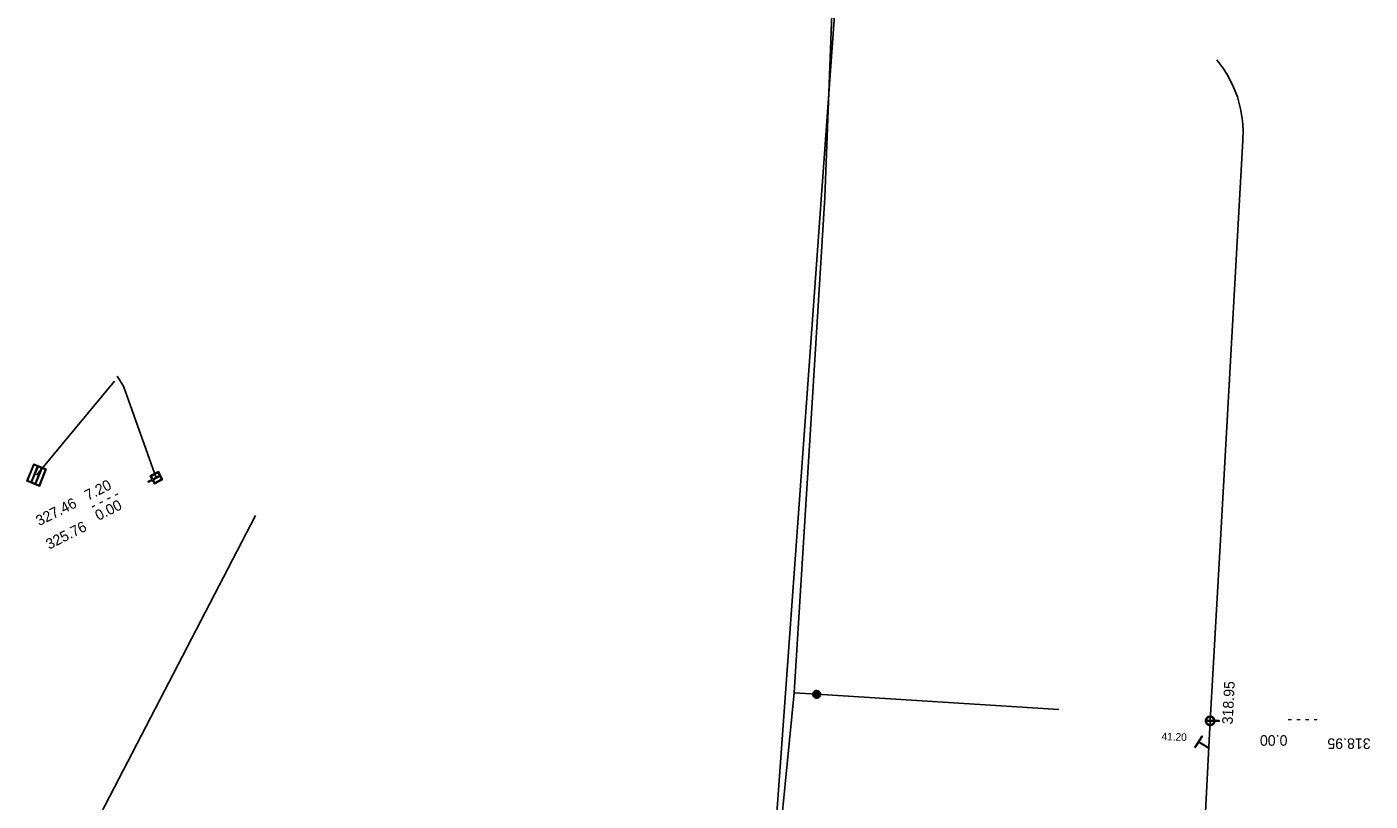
# Model space of a CAD drawing. Extents: x -818065 to -817466, y -1067968 to -1067520.
# Drawn here: x -817766.5 to -817677.6, y -1067753 to -1067701.8 of the extents above; entities that cross this region are included whole.
import ezdxf

# ---------------------------------------------------------------- set-up
doc = ezdxf.new("R2010")
doc.units = 0
doc.layers.add('Default', color=7, linetype='Continuous')
doc.layers.add('Level 0', color=7, linetype='Continuous')

msp = doc.modelspace()

# ---------------------------------------------------------------- linework, layer by layer
at = {"layer": 'Default'}
for points in [[(-817765.193, -1067731.046), (-817765.641, -1067732.16), (-817766.477, -1067731.822), (-817766.027, -1067730.709), (-817765.193, -1067731.046)], [(-817765.774, -1067730.852), (-817766.007, -1067730.758), (-817766.428, -1067731.801), (-817766.196, -1067731.895), (-817765.774, -1067730.852)], [(-817765.51, -1067730.959), (-817765.739, -1067730.866), (-817766.161, -1067731.909), (-817765.932, -1067732.002), (-817765.51, -1067730.959)], [(-817765.475, -1067730.973), (-817765.897, -1067732.016), (-817765.662, -1067732.111), (-817765.241, -1067731.068), (-817765.475, -1067730.973)], [(-817758.168, -1067731.762), (-817758.436, -1067731.898), (-817758.458, -1067731.854), (-817758.191, -1067731.718), (-817758.316, -1067731.473), (-817757.781, -1067731.2), (-817757.509, -1067731.735), (-817758.043, -1067732.007), (-817758.168, -1067731.762)], [(-817758.147, -1067731.696), (-817757.7, -1067731.468), (-817757.803, -1067731.266), (-817758.249, -1067731.494), (-817758.147, -1067731.696)], [(-817758.124, -1067731.739), (-817758.022, -1067731.941), (-817757.575, -1067731.713), (-817757.678, -1067731.512), (-817758.124, -1067731.739)], [(-817688.474, -1067747.665), (-817687.977, -1067747.665)], [(-817687.977, -1067747.715), (-817688.474, -1067747.715)], [(-817687.926, -1067747.665), (-817687.625, -1067747.665), (-817687.625, -1067747.715), (-817687.926, -1067747.715)], [(-817688.339, -1067749.492), (-817688.979, -1067749.092), (-817689.204, -1067749.452), (-817689.23, -1067749.436), (-817688.764, -1067748.692), (-817688.738, -1067748.707), (-817688.963, -1067749.066), (-817688.313, -1067749.473), (-817688.314, -1067749.493), (-817688.339, -1067749.492)]]:
    msp.add_lwpolyline(points, dxfattribs=at)
for points in [[(-817714.223, -1067745.683), (-817714.161, -1067745.687), (-817714.103, -1067745.724), (-817714.046, -1067745.76), (-817714.016, -1067745.822), (-817713.987, -1067745.885), (-817713.991, -1067745.95), (-817713.996, -1067746.015), (-817714.033, -1067746.072), (-817714.07, -1067746.129), (-817714.132, -1067746.158), (-817714.193, -1067746.186), (-817714.258, -1067746.182), (-817714.323, -1067746.177), (-817714.38, -1067746.14), (-817714.437, -1067746.103), (-817714.466, -1067746.042), (-817714.495, -1067745.98), (-817714.49, -1067745.915), (-817714.486, -1067745.85), (-817714.448, -1067745.792), (-817714.41, -1067745.734), (-817714.348, -1067745.706), (-817714.287, -1067745.678), (-817714.223, -1067745.683)], [(-817714.225, -1067745.706), (-817714.282, -1067745.702), (-817714.338, -1067745.728), (-817714.394, -1067745.753), (-817714.428, -1067745.805), (-817714.463, -1067745.858), (-817714.467, -1067745.917), (-817714.471, -1067745.975), (-817714.445, -1067746.031), (-817714.419, -1067746.087), (-817714.367, -1067746.121), (-817714.315, -1067746.154), (-817714.257, -1067746.158), (-817714.198, -1067746.162), (-817714.142, -1067746.136), (-817714.086, -1067746.11), (-817714.052, -1067746.059), (-817714.019, -1067746.007), (-817714.015, -1067745.948), (-817714.011, -1067745.889), (-817714.037, -1067745.833), (-817714.064, -1067745.776), (-817714.116, -1067745.743), (-817714.168, -1067745.71), (-817714.225, -1067745.706)], [(-817714.226, -1067745.723), (-817714.173, -1067745.727), (-817714.126, -1067745.757), (-817714.078, -1067745.788), (-817714.053, -1067745.84), (-817714.028, -1067745.892), (-817714.032, -1067745.947), (-817714.036, -1067746.001), (-817714.066, -1067746.049), (-817714.097, -1067746.097), (-817714.149, -1067746.121), (-817714.201, -1067746.145), (-817714.256, -1067746.141), (-817714.31, -1067746.137), (-817714.358, -1067746.106), (-817714.406, -1067746.075), (-817714.43, -1067746.024), (-817714.453, -1067745.972), (-817714.45, -1067745.918), (-817714.446, -1067745.863), (-817714.414, -1067745.815), (-817714.383, -1067745.766), (-817714.331, -1067745.743), (-817714.279, -1067745.72), (-817714.226, -1067745.723)], [(-817714.228, -1067745.745), (-817714.306, -1067745.74), (-817714.364, -1067745.791), (-817714.422, -1067745.842), (-817714.428, -1067745.919), (-817714.433, -1067745.997), (-817714.382, -1067746.055), (-817714.331, -1067746.114), (-817714.254, -1067746.119), (-817714.176, -1067746.125), (-817714.118, -1067746.074), (-817714.059, -1067746.023), (-817714.054, -1067745.946), (-817714.048, -1067745.868), (-817714.099, -1067745.809), (-817714.149, -1067745.751), (-817714.228, -1067745.745)], [(-817714.23, -1067745.768), (-817714.161, -1067745.773), (-817714.117, -1067745.824), (-817714.073, -1067745.875), (-817714.077, -1067745.943), (-817714.082, -1067746.011), (-817714.133, -1067746.056), (-817714.185, -1067746.1), (-817714.253, -1067746.095), (-817714.321, -1067746.091), (-817714.365, -1067746.039), (-817714.41, -1067745.988), (-817714.405, -1067745.92), (-817714.4, -1067745.852), (-817714.349, -1067745.808), (-817714.298, -1067745.763), (-817714.23, -1067745.768)], [(-817714.231, -1067745.788), (-817714.291, -1067745.784), (-817714.336, -1067745.823), (-817714.381, -1067745.862), (-817714.385, -1067745.922), (-817714.389, -1067745.981), (-817714.35, -1067746.026), (-817714.311, -1067746.072), (-817714.251, -1067746.076), (-817714.192, -1067746.08), (-817714.146, -1067746.041), (-817714.101, -1067746.002), (-817714.097, -1067745.942), (-817714.093, -1067745.882), (-817714.132, -1067745.837), (-817714.171, -1067745.792), (-817714.231, -1067745.788)], [(-817714.232, -1067745.808), (-817714.18, -1067745.811), (-817714.146, -1067745.85), (-817714.112, -1067745.889), (-817714.116, -1067745.941), (-817714.12, -1067745.993), (-817714.159, -1067746.027), (-817714.198, -1067746.061), (-817714.25, -1067746.057), (-817714.301, -1067746.053), (-817714.335, -1067746.014), (-817714.369, -1067745.975), (-817714.365, -1067745.924), (-817714.362, -1067745.872), (-817714.323, -1067745.838), (-817714.284, -1067745.804), (-817714.232, -1067745.808)], [(-817714.234, -1067745.831), (-817714.276, -1067745.828), (-817714.308, -1067745.855), (-817714.339, -1067745.883), (-817714.342, -1067745.925), (-817714.345, -1067745.967), (-817714.318, -1067745.999), (-817714.29, -1067746.03), (-817714.248, -1067746.033), (-817714.206, -1067746.036), (-817714.174, -1067746.009), (-817714.143, -1067745.981), (-817714.14, -1067745.939), (-817714.137, -1067745.897), (-817714.164, -1067745.865), (-817714.192, -1067745.834), (-817714.234, -1067745.831)], [(-817714.235, -1067745.848), (-817714.2, -1067745.85), (-817714.177, -1067745.877), (-817714.154, -1067745.903), (-817714.157, -1067745.938), (-817714.159, -1067745.973), (-817714.186, -1067745.996), (-817714.212, -1067746.019), (-817714.247, -1067746.016), (-817714.282, -1067746.014), (-817714.305, -1067745.987), (-817714.327, -1067745.961), (-817714.325, -1067745.926), (-817714.322, -1067745.891), (-817714.296, -1067745.868), (-817714.27, -1067745.846), (-817714.235, -1067745.848)], [(-817714.237, -1067745.87), (-817714.262, -1067745.868), (-817714.282, -1067745.885), (-817714.301, -1067745.902), (-817714.303, -1067745.928), (-817714.305, -1067745.954), (-817714.288, -1067745.973), (-817714.271, -1067745.993), (-817714.245, -1067745.995), (-817714.219, -1067745.996), (-817714.2, -1067745.979), (-817714.18, -1067745.962), (-817714.178, -1067745.937), (-817714.177, -1067745.911), (-817714.193, -1067745.891), (-817714.21, -1067745.872), (-817714.237, -1067745.87)], [(-817714.238, -1067745.893), (-817714.222, -1067745.894), (-817714.211, -1067745.906), (-817714.201, -1067745.918), (-817714.202, -1067745.935), (-817714.203, -1067745.951), (-817714.215, -1067745.962), (-817714.227, -1067745.972), (-817714.244, -1067745.971), (-817714.26, -1067745.97), (-817714.27, -1067745.958), (-817714.281, -1067745.946), (-817714.28, -1067745.93), (-817714.279, -1067745.913), (-817714.267, -1067745.903), (-817714.254, -1067745.892), (-817714.238, -1067745.893)], [(-817714.239, -1067745.909), (-817714.249, -1067745.908), (-817714.256, -1067745.914), (-817714.264, -1067745.921), (-817714.264, -1067745.931), (-817714.265, -1067745.94), (-817714.259, -1067745.948), (-817714.252, -1067745.955), (-817714.243, -1067745.956), (-817714.233, -1067745.956), (-817714.225, -1067745.95), (-817714.218, -1067745.944), (-817714.218, -1067745.934), (-817714.217, -1067745.924), (-817714.223, -1067745.917), (-817714.229, -1067745.91), (-817714.239, -1067745.909)], [(-817687.926, -1067747.715), (-817687.93, -1067747.777), (-817687.965, -1067747.839), (-817688.004, -1067747.911), (-817688.076, -1067747.95), (-817688.147, -1067747.99), (-817688.225, -1067747.99), (-817688.304, -1067747.99), (-817688.376, -1067747.95), (-817688.448, -1067747.909), (-817688.487, -1067747.838), (-817688.525, -1067747.766), (-817688.525, -1067747.69), (-817688.525, -1067747.614), (-817688.487, -1067747.543), (-817688.448, -1067747.471), (-817688.376, -1067747.43), (-817688.304, -1067747.39), (-817688.225, -1067747.39), (-817688.147, -1067747.39), (-817688.076, -1067747.43), (-817688.004, -1067747.469), (-817687.965, -1067747.541), (-817687.93, -1067747.603), (-817687.926, -1067747.665)], [(-817687.977, -1067747.665), (-817687.98, -1067747.616), (-817688.009, -1067747.565), (-817688.042, -1067747.505), (-817688.101, -1067747.473), (-817688.16, -1067747.44), (-817688.225, -1067747.44), (-817688.29, -1067747.44), (-817688.35, -1067747.473), (-817688.41, -1067747.507), (-817688.443, -1067747.567), (-817688.47, -1067747.618), (-817688.474, -1067747.665)], [(-817688.474, -1067747.715), (-817688.47, -1067747.762), (-817688.443, -1067747.814), (-817688.41, -1067747.873), (-817688.35, -1067747.907), (-817688.29, -1067747.94), (-817688.225, -1067747.94), (-817688.16, -1067747.94), (-817688.101, -1067747.907), (-817688.042, -1067747.875), (-817688.009, -1067747.815), (-817687.98, -1067747.764), (-817687.977, -1067747.715)]]:
    msp.add_open_spline(points, degree=3, dxfattribs=at)
at = {"layer": 'Level 0'}
for p, q in [((-817713.714, -1067713.063), (-817713.001, -1067694.617)), ((-817712.69, -1067695.69), (-817718.04, -1067769.78)), ((-817687.79, -1067703.97), (-817687.319, -1067704.595)), ((-817687.319, -1067704.595), (-817687.013, -1067705.091)), ((-817687.013, -1067705.091), (-817686.676, -1067705.765)), ((-817686.676, -1067705.765), (-817686.424, -1067706.421)), ((-817686.424, -1067706.421), (-817686.209, -1067707.211)), ((-817686.209, -1067707.211), (-817686.087, -1067707.971)), ((-817686.087, -1067707.971), (-817686.045, -1067708.629)), ((-817686.045, -1067708.629), (-817686.061, -1067709.297)), ((-817686.061, -1067709.297), (-817687.547, -1067735.725)), ((-817714.134, -1067719.875), (-817713.714, -1067713.063)), ((-817715.737, -1067745.839), (-817714.134, -1067719.875)), ((-817765.84, -1067731.44), (-817760.68, -1067725.23)), ((-817760.077, -1067725.544), (-817760.5, -1067724.88)), ((-817757.92, -1067731.61), (-817760.077, -1067725.544)), ((-817763.763, -1067758.013), (-817751.347, -1067734.113)), ((-817687.547, -1067735.725), (-817688.22, -1067747.69)), ((-817717.374, -1067762.417), (-817715.737, -1067745.839)), ((-817715.737, -1067745.839), (-817714.241, -1067745.932)), ((-817714.241, -1067745.932), (-817698.235, -1067746.931)), ((-817688.22, -1067747.69), (-817690.294, -1067788.136))]:
    msp.add_line(p, q, dxfattribs=at)

# ---------------------------------------------------------------- texts
for s, height, rotation, p in [('7.20', 0.7, 27, (-817762.434, -1067733.142)), ('- - - -', 0.7, 27, (-817762.088, -1067733.807)), ('327.46', 0.7, 27, (-817765.662, -1067734.818)), ('0.00', 0.7, 27, (-817761.742, -1067734.473)), ('325.76', 0.7, 27, (-817765.001, -1067736.372)), ('318.95', 0.7, 87, (-817686.739, -1067747.939)), ('41.20', 0.5, 358, (-817691.448, -1067748.96)), ('0.00', 0.7, 180, (-817683.109, -1067748.633)), ('318.95', 0.7, 180, (-817677.606, -1067748.847))]:
    msp.add_text(s, height=height, rotation=rotation, dxfattribs=at).set_placement(p)
msp.add_text('- - - -', height=0.7, dxfattribs=at).set_placement((-817683.109, -1067747.883))

doc.saveas('drawing.dxf')
